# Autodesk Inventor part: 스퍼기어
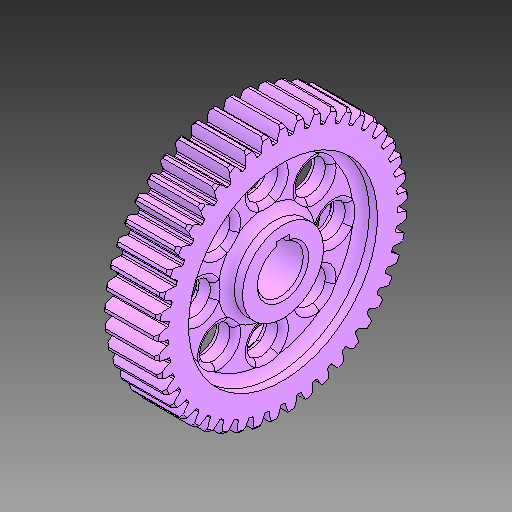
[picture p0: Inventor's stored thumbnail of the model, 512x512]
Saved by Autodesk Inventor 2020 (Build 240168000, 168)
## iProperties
Created: 2025-03
Part Number: 스퍼기어
Material: 강철, 합금
Document SubType Name: Modeling
Designer: CA01
Density: 7.73 g/cm^3
Appearance: 기본값
Author: jhkim
Sending System: Autodesk Inventor 2025
Preprocessor: ST-DEVELOPER v20
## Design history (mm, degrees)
feature "솔리드1"
node "솔리드2"
